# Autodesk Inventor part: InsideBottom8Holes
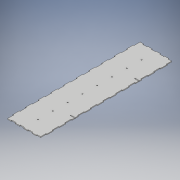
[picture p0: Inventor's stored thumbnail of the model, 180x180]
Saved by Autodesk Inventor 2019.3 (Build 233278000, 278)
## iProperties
Created: 2020-02
Part Number: InsideBottom8Holes
Material: Generic
Document SubType Name: Modeling
Designer: KrystynWikoff
Density: 1 g/cm^3
Appearance: Default
Author: KrystynWikoff
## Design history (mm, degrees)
sketch "Sketch1"
  geometry: L1 (0, 0)-(101.6, 0); L2 (101.6, 0)-(101.6, -398.424); L3 (101.6, -398.424)-(0, -398.424); L4 (0, -398.424)-(0, 0)
  constraints: 8 end point, 2 parallel, 1 horizontal, 1 perpendicular
  dimensions: "d0" = 398.4244 distance of L3.end L1.start; "d1" = 101.6 distance of L1.start L1.end
extrude "Extrusion1" new body sketch "Sketch1" distance "d2" = 2.3622; taper "d3" = 0 deg
sketch "Sketch2" dims "d18" = 25.4
  geometry: L1 (-101.6, 0)-(-99.238, 0); L2 (-99.238, 0)-(-99.238, 18.237); L3 (-99.238, 18.237)-(-101.6, 18.237); L4 (-101.6, 18.237)-(-101.6, 0); L5 (-101.6, 0)-(0, 0) reference; L6 (-101.6, 398.424)-(-101.6, 0) reference; L7 (-101.6, 398.424)-(-99.238, 398.424); L8 (-99.238, 398.424)-(-99.238, 380.187); L9 (-99.238, 380.187)-(-101.6, 380.187); L10 (-101.6, 380.187)-(-101.6, 398.424); L11 (-101.6, 37.287)-(-99.238, 37.287); L12 (-99.238, 37.287)-(-99.238, 56.337); L13 (-99.238, 56.337)-(-101.6, 56.337); L14 (-101.6, 56.337)-(-101.6, 37.287); L15 (-99.238, 94.437)-(-101.6, 94.437); L16 (-99.238, 75.387)-(-99.238, 94.437); L17 (-101.6, 94.437)-(-101.6, 75.387); L18 (-101.6, 75.387)-(-99.238, 75.387); L19 (-99.238, 132.537)-(-101.6, 132.537); L20 (-99.238, 113.487)-(-99.238, 132.537); L21 (-101.6, 132.537)-(-101.6, 113.487); L22 (-101.6, 113.487)-(-99.238, 113.487); L23 (-99.238, 170.637)-(-101.6, 170.637); L24 (-99.238, 151.587)-(-99.238, 170.637); L25 (-101.6, 170.637)-(-101.6, 151.587); L26 (-101.6, 151.587)-(-99.238, 151.587); L27 (-99.238, 208.737)-(-101.6, 208.737); L28 (-99.238, 189.687)-(-99.238, 208.737); L29 (-101.6, 208.737)-(-101.6, 189.687); L30 (-101.6, 189.687)-(-99.238, 189.687); L31 (-99.238, 246.837)-(-101.6, 246.837); L32 (-99.238, 227.787)-(-99.238, 246.837); L33 (-101.6, 246.837)-(-101.6, 227.787); L34 (-101.6, 227.787)-(-99.238, 227.787); L35 (-99.238, 284.937)-(-101.6, 284.937); L36 (-99.238, 265.887)-(-99.238, 284.937); L37 (-101.6, 284.937)-(-101.6, 265.887); L38 (-101.6, 265.887)-(-99.238, 265.887); L39 (-99.238, 323.037)-(-101.6, 323.037); L40 (-99.238, 303.987)-(-99.238, 323.037); L41 (-101.6, 323.037)-(-101.6, 303.987); L42 (-101.6, 303.987)-(-99.238, 303.987); L43 (-99.238, 361.137)-(-101.6, 361.137); L44 (-99.238, 342.087)-(-99.238, 361.137); L45 (-101.6, 361.137)-(-101.6, 342.087); L46 (-101.6, 342.087)-(-99.238, 342.087)
  constraints: 88 end point, 6 parallel, 3 horizontal, 3 perpendicular, 1 point on line, 1 vertical, 64 other
  dimensions: "d4" = 0 distance between parallel lines of L1 L5; "d5" = 18.2372 distance of L1.end L2.end; "d6" = 2.3622 distance of L1.start L1.end; "d7" = 0 distance between parallel lines of L6 L4; "d8" = 2.3622 distance of L8.end L9.end; "d9" = 18.2372 distance of L7.end L8.end; "d10" = 19.05 distance of L11.end L12.end; "d11" = 19.05 distance between parallel lines of L11 L3; "d12" = 2.3622 distance of L11.start L11.end; "d15" = 38.1 distance of L12.end L15.start
extrude "Extrusion2" cut sketch "Sketch2" distance "d20" = 2.3622; taper "d21" = 0 deg
sketch "Sketch3" dims "d30" = 25.4, "d41" = 25.4
  geometry: L1 (0, 0)-(-99.238, 0) reference; L2 (-76.2, 0)-(-88.9, 0); L3 (-88.9, 0)-(-88.9, 2.362); L4 (-88.9, 2.362)-(-76.2, 2.362); L5 (-76.2, 2.362)-(-76.2, 0); L6 (-101.6, 37.287)-(-101.6, 18.237) reference; L7 (-50.8, 0)-(-63.5, 0); L8 (-63.5, 0)-(-63.5, 2.362); L9 (-63.5, 2.362)-(-50.8, 2.362); L10 (-50.8, 2.362)-(-50.8, 0); L11 (-25.4, 0)-(-38.1, 0); L12 (-38.1, 0)-(-38.1, 2.362); L13 (-38.1, 2.362)-(-25.4, 2.362); L14 (-25.4, 2.362)-(-25.4, 0); L15 (0, 0)-(-12.7, 0); L16 (-12.7, 0)-(-12.7, 2.362); L17 (-12.7, 2.362)-(0, 2.362); L18 (0, 2.362)-(0, 0); L19 (-88.9, 398.424)-(-76.2, 398.424); L20 (-76.2, 398.424)-(-76.2, 396.062); L21 (-76.2, 396.062)-(-88.9, 396.062); L22 (-88.9, 396.062)-(-88.9, 398.424); L23 (0, 398.424)-(-99.238, 398.424) reference; L24 (-101.6, 380.187)-(-101.6, 361.137) reference; L25 (-50.8, 398.424)-(-50.8, 396.062); L26 (-50.8, 396.062)-(-63.5, 396.062); L27 (-63.5, 396.062)-(-63.5, 398.424); L28 (-63.5, 398.424)-(-50.8, 398.424); L29 (-25.4, 398.424)-(-25.4, 396.062); L30 (-25.4, 396.062)-(-38.1, 396.062); L31 (-38.1, 396.062)-(-38.1, 398.424); L32 (-38.1, 398.424)-(-25.4, 398.424); L33 (0, 398.424)-(0, 396.062); L34 (0, 396.062)-(-12.7, 396.062); L35 (-12.7, 396.062)-(-12.7, 398.424); L36 (-12.7, 398.424)-(0, 398.424)
  constraints: 64 end point, 4 horizontal, 4 parallel, 2 perpendicular, 1 point on line, 48 other
  dimensions: "d22" = 2.3622 distance of L4.end L2.start; "d23" = 12.7 distance between parallel lines of L6 L3; "d24" = 12.7 distance of L3.end L4.end; "d27" = 25.4 distance of L2.start L7.start; "d32" = 2.3622 distance of L19.end L20.end; "d33" = 0 distance between parallel lines of L23 L19; "d34" = 12.7 distance between parallel lines of L24 L22; "d35" = 12.7 distance of L20.end L21.end; "d38" = 25.4 distance of L20.end L25.end
extrude "Extrusion3" cut sketch "Sketch3" distance "d43" = 2.3622; taper "d44" = 0 deg
sketch "Sketch4"
  geometry: L1 (0, 398.424)-(0, 0) reference; L2 (0, 103.962)-(-12.7, 103.962); L3 (-12.7, 103.962)-(-12.7, 101.6); L4 (-12.7, 101.6)-(0, 101.6); L5 (0, 101.6)-(0, 103.962); L6 (-99.238, 0)-(0, 0) reference; L7 (0, 296.824)-(-12.7, 296.824); L8 (-12.7, 296.824)-(-12.7, 294.462); L9 (-12.7, 294.462)-(0, 294.462); L10 (0, 294.462)-(0, 296.824); L11 (0, 398.424)-(-50.8, 398.424) reference; 2 further points
  constraints: 16 end point, 4 parallel, 2 horizontal, 2 perpendicular, 2 point on line
  dimensions: "d45" = 2.3622 distance of L2.end L3.end; "d46" = 101.6 distance between parallel lines of L6 L4; "d47" = 12.7 distance of L3.end L4.end; "d48" = 2.3622 distance of L7.end L8.end; "d49" = 101.6 distance between parallel lines of L7 L11; "d50" = 12.7 distance of L8.end L9.end
extrude "Extrusion4" cut sketch "Sketch4" distance "d51" = 25.4; taper "d52" = 0 deg
sketch "Sketch6" dims "d61" = 25.4
  geometry: L1 (-99.238, 0)-(0, 0) reference; L2 (-99.238, 56.337)-(-99.238, 37.287) reference; L3 (-101.6, 37.287)-(-101.6, 18.237) reference; C1 r 1.511 at (-50.8, 42.939); C2 r 1.511 at (-50.8, 87.389); C3 r 1.511 at (-50.8, 131.839); C4 r 1.511 at (-50.8, 176.289); C5 r 1.511 at (-50.8, 220.739); C6 r 1.511 at (-50.8, 265.189); C7 r 1.511 at (-50.8, 309.639); C8 r 1.511 at (-50.8, 354.089); 1 further point
  constraints: 8 centre point, 1 vertical, 14 other
  dimensions: "d53" = 3.0226 diameter of C1; "d54" = 42.9387 distance from line of L1 C1.centre; "d58" = 44.45 distance of C1.centre C2.centre; "d65" = 50.8 distance from line of L3 C1.centre
extrude "Extrusion5" cut sketch "Sketch6" distance "d63" = 25.4; taper "d64" = 0 deg
sketch "Sketch7" dims "d76" = 25.4
  geometry: L1 (0, 0)-(-2.362, 0); L2 (-2.362, 0)-(-2.362, 18.237); L3 (-2.362, 18.237)-(0, 18.237); L4 (0, 18.237)-(0, 0); L5 (0, 101.6)-(0, 2.362) reference; L6 (0, 37.287)-(-2.362, 37.287); L7 (-2.362, 37.287)-(-2.362, 56.337); L8 (-2.362, 56.337)-(0, 56.337); L9 (0, 56.337)-(0, 37.287); L10 (0, 75.387)-(-2.362, 75.387); L11 (-2.362, 75.387)-(-2.362, 94.437); L12 (-2.362, 94.437)-(0, 94.437); L13 (0, 94.437)-(0, 75.387); L14 (0, 113.487)-(-2.362, 113.487); L15 (-2.362, 113.487)-(-2.362, 132.537); L16 (-2.362, 132.537)-(0, 132.537); L17 (0, 132.537)-(0, 113.487); L18 (0, 151.587)-(-2.362, 151.587); L19 (-2.362, 151.587)-(-2.362, 170.637); L20 (-2.362, 170.637)-(0, 170.637); L21 (0, 170.637)-(0, 151.587); L22 (0, 189.687)-(-2.362, 189.687); L23 (-2.362, 189.687)-(-2.362, 208.737); L24 (-2.362, 208.737)-(0, 208.737); L25 (0, 208.737)-(0, 189.687); L26 (0, 227.787)-(-2.362, 227.787); L27 (-2.362, 227.787)-(-2.362, 246.837); L28 (-2.362, 246.837)-(0, 246.837); L29 (0, 246.837)-(0, 227.787); L30 (0, 265.887)-(-2.362, 265.887); L31 (-2.362, 265.887)-(-2.362, 284.937); L32 (-2.362, 284.937)-(0, 284.937); L33 (0, 284.937)-(0, 265.887); L34 (0, 303.987)-(-2.362, 303.987); L35 (-2.362, 303.987)-(-2.362, 323.037); L36 (-2.362, 323.037)-(0, 323.037); L37 (0, 323.037)-(0, 303.987); L38 (0, 342.087)-(-2.362, 342.087); L39 (-2.362, 342.087)-(-2.362, 361.137); L40 (-2.362, 361.137)-(0, 361.137); L41 (0, 361.137)-(0, 342.087); L42 (0, 398.424)-(-2.362, 398.424); L43 (-2.362, 398.424)-(-2.362, 380.187); L44 (-2.362, 380.187)-(0, 380.187); L45 (0, 380.187)-(0, 398.424); L46 (-12.7, 398.424)-(-25.4, 398.424) reference; L47 (-12.7, 396.062)-(-12.7, 398.424) reference
  constraints: 88 end point, 6 parallel, 3 horizontal, 3 perpendicular, 1 point on line, 1 vertical, 64 other
  dimensions: "d66" = 2.3622 distance of L2.end L3.end; "d67" = 18.2372 distance of L1.end L2.end; "d68" = 2.3622 distance of L6.start L6.end; "d69" = 19.05 distance of L6.end L7.end; "d70" = 19.05 distance between parallel lines of L3 L6; "d73" = 38.1 distance of L6.start L10.start; "d78" = 18.2372 distance of L42.end L43.end; "d79" = 2.3622 distance of L43.end L44.end; "d80" = 18.2372 distance between parallel lines of L46 L44; "d81" = 12.7 distance between parallel lines of L47 L45
extrude "Extrusion6" cut sketch "Sketch7" extent not by distance; stored distance "d82" = 0; taper "d83" = 0 deg
body "Solid1"
